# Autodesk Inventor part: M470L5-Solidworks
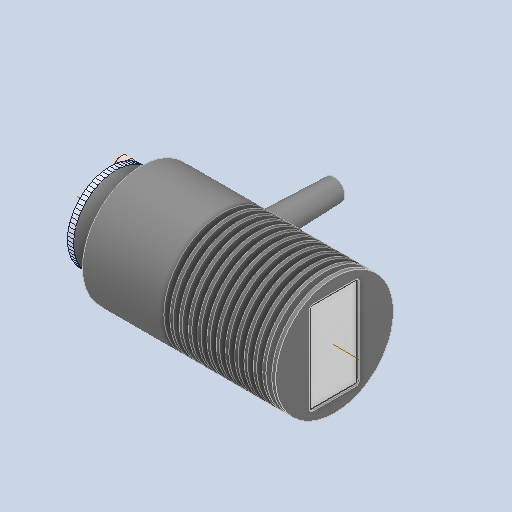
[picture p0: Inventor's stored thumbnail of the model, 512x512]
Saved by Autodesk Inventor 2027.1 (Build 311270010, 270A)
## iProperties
Part Number: M470L5-Solidworks
Material: Generic
Document SubType Name: Modeling
Designer: dunge
Density: 1 g/cm^3
Appearance: Default
Author: dunge
Sending System: SOLIDWORKS 2019
Last Saved Date: 2021-09-22
last saved by: phittmair
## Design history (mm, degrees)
feature "solid1"
feature "solid2"
feature "solid3"
feature "solid4"
feature "solid5"
feature "solid6"
feature "solid7"
feature "solid8"
feature "solid9"
feature "solid10"
feature "solid11"
feature "solid12"
feature "solid13"
feature "solid14"
feature "solid15"
feature "solid16"
feature "solid17"
feature "solid18"
feature "solid19"
feature "solid20"
feature "solid21"
workpoint "Work Point1"
  workaxis "Work Axis1"
body "Solid1"
body "Solid2"
body "Solid3"
body "Solid4"
body "Solid5"
body "Solid6"
body "Solid7"
body "Solid8"
body "Solid9"
body "Solid10"
body "Solid11"
body "Solid12"
body "Solid13"
body "Solid14"
body "Solid15"
body "Solid16"
body "Solid17"
body "Solid18"
body "Solid19"
body "Solid20"
body "Solid21"
